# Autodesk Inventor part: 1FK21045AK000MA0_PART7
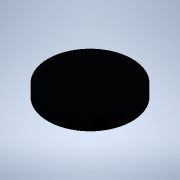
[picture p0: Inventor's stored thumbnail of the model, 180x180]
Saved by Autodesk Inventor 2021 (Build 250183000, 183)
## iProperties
Created: 2025-04
Part Number: 1FK21045AK000MA0_PART7
Material: Generic
Catalog Web Link: www.3dfindit.com
Description: -Servo synchronous motor
Document SubType Name: Modeling
Designer: psAdmin
Mass: 0.299142 g
Surface Area: 3.8585 cm^2
Volume: 0.299142 cm^3
Density: 1 g/cm^3
Appearance: PSOLRGB-38-46-56
Category: PARTsolutions
Title: 1FK21045AK000MA0_PART7
Author: Cadenas PARTsolutions
Comments: Servo synchronous motor
Sending System: PARTsolutions
Preprocessor: ST-DEVELOPER v19.3
PSOL_IDENT_0: {$CADENAS_DATA/23d-libs/siemens_ag/_cat_/3d/2f/1fk21045ak000ma0.prj},213 {VTYP=3D},{NB=1FK21045AK000
PSOL_IDENT_1: MA0_PART7},{LINA=1FK21045AK000MA0_PART7},{NN=1FK21045AK000MA0_PART7},{NOPRJ=TRUE},{DATE=19.08.2025 1
PSOL_IDENT_2: 4:00:34},{GEOMDATE=30.07.2025 02:01:24},{VERSION=},{LINEID=10},{WBVAR=},{WBNUMERIC=}  {NB=1FK21045AK
PSOL_IDENT_3: 000MA0_PART7},{LINA=1FK21045AK000MA0_PART7},{KT=DUMMY},{PREVIEW=../../../_pool_/a9/69/p_d211_xx_0081
PSOL_IDENT_4: 8j.png},{DESCSHORT=SIMOTICS S-1FK2 HD, SINAMICS S210 3AC 400V-480V, 1.7 Nm, 6000 rpm},{DESCLONG=SIMO
PSOL_IDENT_5: TICS S-1FK2 HD servo motor M0=2.4 Nm; PN = 1.07 kW at nN=6000 rpm (380-480 V); PN = 0.75 kW at nN=30
PSOL_IDENT_6: 00 rpm (200-240 V); degree of protection IP64; cylindrical shaft D19x40mm; absolute encoder 22-bit +
PSOL_IDENT_7: 12-bit multiturn (encoder AM22DQC); with OCC interface; plug size M17, rotatable; SIMOTICS S-1FK2 s
PSOL_IDENT_8: ervomotorfor a wide range of uses in industrial environments. SIMOTICS S‑1FK2 servomotors are compac
PSOL_IDENT_9: t synchronous motors with a high dynamic performance that set themselves apart as a result of their
PSOL_IDENT_10: high power density, degree of protection and overload capability. The motors are available in two va
PSOL_IDENT_11: riants: as High Dynamic variant (highest dynamic performance as a result of the low intrinsic moment
PSOL_IDENT_12: of inertia for applications demanding a high dynamic performance with low moved masses) - and as Co
PSOL_IDENT_13: mpact variant (precise and stable closed-loop control for medium up to large moved masses as a resul
PSOL_IDENT_14: t of a medium intrinsic moment of inertia). SIMOTICSS‑1FK2 servomotors fully exploit their strengths
PSOL_IDENT_15: in a system with the SINAMICSS210 frequency converter and simple connection using the one cable con
PSOL_IDENT_16: nection (OCC). Advantages include the short control and positioning times, fast and precise correcti
PSOL_IDENT_17: on of disturbing quantities as well as stable control with a high dynamic performance. The servo mot
PSOL_IDENT_18: ors can be configured to address a wide range of requirements. For example with and without holding
PSOL_IDENT_19: brake, IP64 or IP65 degree of protection, singleturn or multiturn absolute encoders - to name just a
PSOL_IDENT_20: few. Further, the servomotors are available in different shaft heights extending from 20 to 100. A
PSOL_IDENT_21: shaft sealing ring is available to achieve an IP65 degree of protection and for subsequent mounting
PSOL_IDENT_22: at the motor or as spare part. SIMOTICS - the optimum motor for each and every motion control applic
PSOL_IDENT_23: ation.},{INTNO=804766789342},{SUPPLIERALTNO=1FK2104-5AK00-0MA0},{MANUID=1FK21045AK000MA0},{MANUNAME=
PSOL_IDENT_24: Siemens},{MANUTYPEDESC=Synchronous motor 1FK2-HD 2,39 Nm},{AAU732=SIMOTICS},{AAO057=S-1FK2},{AAU734=
PSOL_IDENT_25: SIMOTICS S-1FK2 HD servo motor M0=2.4 Nm; PN = 1.07 kW at nN=6000 rpm (380-480 V); PN = 0.75 kW at n
PSOL_IDENT_26: N=3000 rpm (200-240 V); degree of protection IP64; cylindrical shaft D19x40mm; absolute encoder 22-b
PSOL_IDENT_27: it + 12-bit multiturn (encoder AM22DQC); with OCC interface; plug size M17, rotatable;},{AAW338=Sync
PSOL_IDENT_28: hronous motor 1FK2-HD 2,39 Nm},{AAO742=SIMOTICS},{AAO663=4042948691151},{NOCUPEROU=1},{PRICEQUANTITY=
PSOL_IDENT_29: 1},{QUANTITYMIN=1},{QUANTITYINT=1},{CTN=85015100},{COO=DE},{AAO676=1FK2104-5AK00-0MA0},{AAO677=Sieme
PSOL_IDENT_30: ns AG},{ORDERUNIT=C62},{CONTENTUNIT=C62}
NB: 1FK21045AK000MA0_PART7
NT: Servo synchronous motor
NBSYN: $MANUID._PART7
LINA: 1FK21045AK000MA0_PART7
CATALOG: SIEMENS
PREVIEW: ../../../_pool_/a9/69/p_d211_xx_00818j.png
DESCSHORT: SIMOTICS S-1FK2 HD, SINAMICS S210 3AC 400V-480V, 1.7 Nm, 6000 rpm
DESCLONG: SIMOTICS S-1FK2 HD servo motor M0=2.4 Nm; PN = 1.07 kW at nN=6000 rpm (380-480 V); PN = 0.75 kW at nN=3000 rpm (200-240 V); degree of protection IP64; cylindric
INTNO: 804766789342
SUPPLIERALTNO: 1FK2104-5AK00-0MA0
MANUID: 1FK21045AK000MA0
MANUNAME: Siemens
MANUTYPEDESC: Synchronous motor 1FK2-HD 2,39 Nm
AAU732: SIMOTICS
AAO057: S-1FK2
AAU734: SIMOTICS S-1FK2 HD servo motor M0=2.4 Nm; PN = 1.07 kW at nN=6000 rpm (380-480 V); PN = 0.75 kW at nN=3000 rpm (200-240 V); degree of protection IP64; cylindric
AAW338: Synchronous motor 1FK2-HD 2,39 Nm
AAO742: SIMOTICS
AAO663: 4042948691151.0
NOCUPEROU: 1
PRICEQUANTITY: 1
QUANTITYMIN: 1
QUANTITYINT: 1
CTN: 85015100
COO: DE
ARTICLENO: 1FK21045AK000MA0_PART7
BOMINFO: 1FK21045AK000MA0_PART7
CREATOR: CADENAS GmbH
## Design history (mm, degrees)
feature "2025_04_17_15_39_51_0697"
body "Solid1"
